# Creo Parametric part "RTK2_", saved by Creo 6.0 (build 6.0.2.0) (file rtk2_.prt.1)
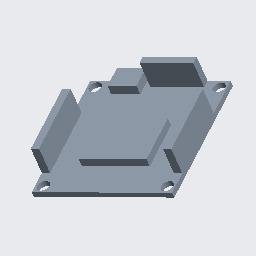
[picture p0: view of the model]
Units: Inch lbm Second (Pro/E Default); INCH, POUND, SECS

Created from: INLBS_PART_SOLID.PRT

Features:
  1. datum plane "RIGHT"
  2. datum plane "TOP"
  3. datum plane "FRONT"
  4. coordinate system
  5. sketch "Sketch 1"
  6. extrusion "Extrude 1"
  7. sketch "Sketch 2"
  8. extrusion "Extrude 2"
  9. sketch "Sketch 3"
  10. extrusion "Extrude 3"
  11. sketch "Sketch 4"
  12. extrusion "Extrude 4"

Surfaces: 27 plane, 4 cylinder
